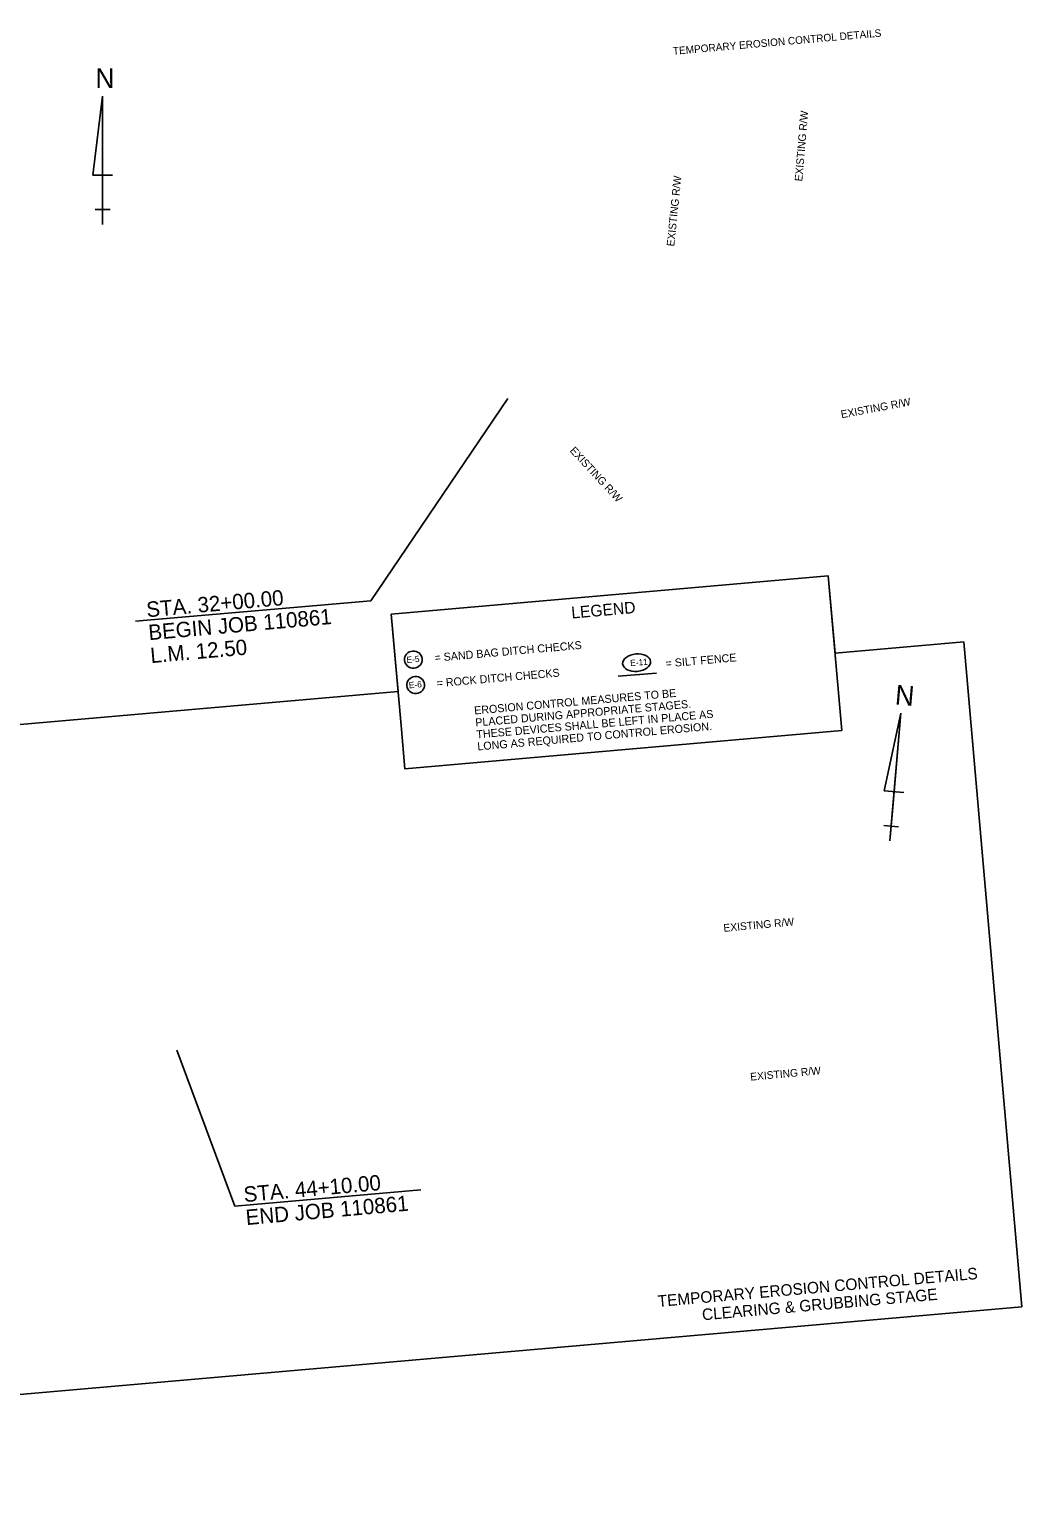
# Model space of a CAD drawing. Extents: x 1734805 to 1736440, y 377441 to 378578.
# Drawn here: x 1735664 to 1736440, y 377441 to 378578 of the extents above; entities that cross this region are included whole.
import ezdxf

# ---------------------------------------------------------------- set-up
doc = ezdxf.new("R2010")
doc.units = 0
for name, color, linetype in [('1', 7, 'Continuous'), ('60', 7, 'Continuous'), ('63', 7, 'Continuous'), ('G-Border-Sheet', 7, 'Continuous'), ('Level 1', 7, 'Continuous'), ('Level 44', 7, 'Continuous'), ('R_Draft', 7, 'Continuous')]:
    doc.layers.add(name, color=color, linetype=linetype)

msp = doc.modelspace()

# ---------------------------------------------------------------- linework, layer by layer
at = {"layer": '1'}
for p, q in [((1735947.4, 378121.3), (1736288.7, 378151.2)), ((1736299.3, 378030.6), (1736288.7, 378151.2)), ((1735955, 378034.5), (1735947.4, 378121.3))]:
    msp.add_line(p, q, dxfattribs=at)
msp.add_lwpolyline([(1735955, 378034.5), (1735957.9, 378000.7), (1736299.3, 378030.6)], dxfattribs=at)
at = {"layer": '63'}
for p, q in [((1735721.9, 378525.7), (1735714.2, 378464.2)), ((1735721.9, 378425.7), (1735721.9, 378525.7)), ((1735721.9, 378525.7), (1735721.9, 378448.8)), ((1735714.2, 378464.2), (1735729.6, 378464.2)), ((1735721.9, 378425.7), (1735721.9, 378448.8)), ((1735721.9, 378437.3), (1735716.1, 378437.3)), ((1735716.1, 378437.3), (1735727.7, 378437.3)), ((1735721.9, 378425.7), (1735721.9, 378437.3)), ((1736345.5, 378044), (1736332.4, 377983.4)), ((1736336.8, 377944.4), (1736345.5, 378044)), ((1736345.5, 378044), (1736338.8, 377967.4)), ((1736332.4, 377983.4), (1736347.8, 377982)), ((1736336.8, 377944.4), (1736338.8, 377967.4)), ((1736337.8, 377955.9), (1736332, 377956.4)), ((1736332, 377956.4), (1736343.5, 377955.4)), ((1736336.8, 377944.4), (1736337.8, 377955.9))]:
    msp.add_line(p, q, dxfattribs=at)
at = {"layer": 'G-Border-Sheet'}
for p, q in [((1736394.5, 378099.7), (1736439.9, 377580.5)), ((1736439.9, 377580.5), (1734850.6, 377441.5))]:
    msp.add_line(p, q, dxfattribs=at)
msp.add_lwpolyline([(1734805.2, 377960.6), (1734905.7, 377969.4), (1734905.7, 377969.4), (1734912, 377897.5), (1735335.4, 377934.5), (1735329.1, 378006.5), (1735952.7, 378061), (1735947.4, 378121.3), (1736288.7, 378151.2), (1736294, 378090.9), (1736394.5, 378099.7)], dxfattribs=at)
at = {"layer": 'Level 1'}
for centre, major_axis, ratio in [((1735964.6, 378085.9), (-6.85, -0.6), 0.97521), ((1736139, 378083.5), (10.9, 1), 0.622952), ((1735966.4, 378066), (-6.85, -0.6), 0.97521)]:
    msp.add_ellipse(centre, major_axis=major_axis, ratio=ratio, dxfattribs=at)
at = {"layer": 'Level 44'}
msp.add_lwpolyline([(1736124.6, 378072.9), (1736154.6, 378075.4)], dxfattribs=at)
at = {"layer": 'R_Draft'}
for points in [[(1736038.5, 378289.8), (1735931.3, 378131.8), (1735747.6, 378115.8)], [(1735780, 377780.8), (1735825.2, 377659.2), (1735970.4, 377671.9)]]:
    msp.add_lwpolyline(points, dxfattribs=at)

# ---------------------------------------------------------------- texts
at = {"layer": '1'}
msp.add_text('TEMPORARY EROSION CONTROL DETAILS', height=5.862, rotation=5, dxfattribs=at).set_placement((1736167.6, 378558.1))
at = {"layer": '60'}
for s, p in [('TEMPORARY EROSION CONTROL DETAILS', (1736155.9, 377580.4)), ('CLEARING & GRUBBING STAGE', (1736190.5, 377569.9))]:
    msp.add_text(s, height=9, rotation=5, dxfattribs=at).set_placement(p)
at = {"layer": '63'}
for rotation, p in [(0, (1735716.3, 378532.1)), (355, (1736340.4, 378050.9))]:
    msp.add_text('N', height=15.4, rotation=rotation, dxfattribs=at).set_placement(p)
at = {"layer": 'Level 1'}
for s, height, p in [('= SAND BAG DITCH CHECKS', 6.25, (1735981.4, 378084.2)), ('E-5', 4.88, (1735959.5, 378083.2)), ('= SILT FENCE', 6.25, (1736161.9, 378079.7)), ('= ROCK DITCH CHECKS', 6.25, (1735983.1, 378064.3)), ('E-11', 4.88, (1736134.2, 378080.7)), ('E-6', 4.88, (1735961.3, 378063.4)), ('EROSION CONTROL MEASURES TO BE', 6.25, (1736012.4, 378043)), ('PLACED DURING APPROPRIATE STAGES. ', 6.25, (1736013.3, 378033.6)), ('THESE DEVICES SHALL BE LEFT IN PLACE AS ', 6.25, (1736014.1, 378024.3)), ('LONG AS REQUIRED TO CONTROL EROSION.', 6.25, (1736014.9, 378014.9))]:
    msp.add_text(s, height=height, rotation=5, dxfattribs=at).set_placement(p)
at = {"layer": 'Level 44'}
msp.add_text('LEGEND', height=9.14, rotation=5, dxfattribs=at).set_placement((1736088.4, 378117.9))
at = {"layer": 'R_Draft'}
for s, height, rotation, p in [('EXISTING R/W', 6, 85.1703, (1736268.4, 378459.1)), ('EXISTING R/W', 6, 84.168, (1736168.4, 378408.3)), ('EXISTING R/W', 6, 10.6188, (1736299.1, 378274.3)), ('EXISTING R/W', 6, 312.768, (1736086.4, 378248.7)), ('STA. 32+00.00', 12, 5.0823, (1735756.6, 378118.9)), ('BEGIN JOB 110861', 12, 5.0823, (1735758.2, 378101)), ('L.M. 12.50', 12, 5.0823, (1735759.7, 378083.1)), ('EXISTING R/W', 6, 5.2121, (1736207.1, 377873.3)), ('EXISTING R/W', 6, 5.2121, (1736228, 377757.1)), ('STA. 44+10.00', 12, 5.0823, (1735832.6, 377662.2)), ('END JOB 110861', 12, 5.0823, (1735834.2, 377644.3))]:
    msp.add_text(s, height=height, rotation=rotation, dxfattribs=at).set_placement(p)

doc.saveas('drawing.dxf')
